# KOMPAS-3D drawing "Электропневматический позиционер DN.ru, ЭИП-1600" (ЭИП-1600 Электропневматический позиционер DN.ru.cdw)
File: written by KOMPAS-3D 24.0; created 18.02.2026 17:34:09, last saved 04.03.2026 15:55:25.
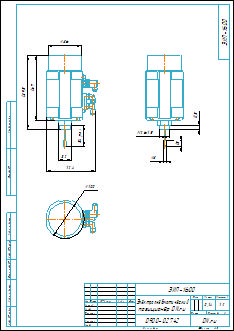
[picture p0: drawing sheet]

Document properties: Автор: R2D2; Форматы листов документа: A3; Полное имя файла: ЭИП-1600 Электропневматический позиционер DN.ru.m3d; Масса: 0.14; Наименование: Электропневматический позиционер DN.ru; Количество листов документа: 1; Примечание: D900-02742

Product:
- Body: Тело 2  | qty 1
    Масса: 9.466594
- Part/product: Электропневматический позиционер DN.ru  | designation ЭИП-1600
    Масса: 0.14
    Раздел спецификации: Прочие изделия
    Примечание: D900-02742

Views: Проекционный вид 2
Referenced files in E:\Работа\Зайцев\Аксессуары для пневмоприводов\Электропневматические позиционеры DN.ru\ЭИП Электропневматический позиционер DN.ru\ЭИП-1600 Электропневматический позиционер DN.ru\5-25\: ЭИП-1600 Электропневматический позиционер DN.ru.m3d
Referenced files in E:\Работа\Зайцев\Для компаса\: чертеж DN.ru А3.cdt
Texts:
  ЭИП-1600
  чертеж DN.ru А3.cdt
  Электропневматический
  позиционер DN.ru
  Электропневматический позиционер DN.ru
  ЭИП-1600 Электропневматический позиционер DN.ru
Dimensions and other numbers on the sheet: 0; 3; 4; 11,5; 15; 8; 26; 1:2; 1; 2; 0,14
